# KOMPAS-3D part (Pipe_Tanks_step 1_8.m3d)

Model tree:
1. X Axis
2. Y Axis
3. Z Axis  (labels: Bend 90 Dn 50; Pipe Dn 50; C:\Program Files\ASCON\KOMPAS-3D V10\Sys\graphic.lyt; Pipe_Tanks_step 1_8.m3d)
     Òîëùèíà ñòåíêè 1 = 1

Referenced files in C:\Documents and Settings\kashirsky\Мои документы\Camtasia Studio\Pipelines3D\Tanks\: Tanks_step 1.a3d, Tanks_step 1.spw
Referenced files in C:\Documents and Settings\kashirsky\Мои документы\Camtasia Studio\Pipelines3D\Tanks\Tanks_step 1_Pipes\: Pipe_Tanks_step 1_8.m3d
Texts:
  Pipe Dn 50
  Steel ASTM A295
  Three Point Plane
  Plane at Angle
  Line and Point Plane
  Axis through Two Vertices
  Axis of Feature
  Axis of Conical Surface
  Axis through Edge
  Trim by Surface
  Trim by Sketch
  Feature with No History
  Intersection Axis of Two Planes
  Two Line Plane
  Line and Face Plane
  Bend by line
  Hole in sheet body
  Cut in sheet body
  Point in CM
  Linear Dimension from Line to Point
  Surface Finish Symbol
  Geometric Tolerance Symbol
  Leader #1
  Leader #2
  Leader #3
  Shape Deviations and Datum
  Node point number
  Mark of coordination axis
  Node point designation
  Mark/Reference designation with leader
  Mark/reference designation on line
  Mark/Reference designation without leader
  Bend 90 Dn 50
  Plane of section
